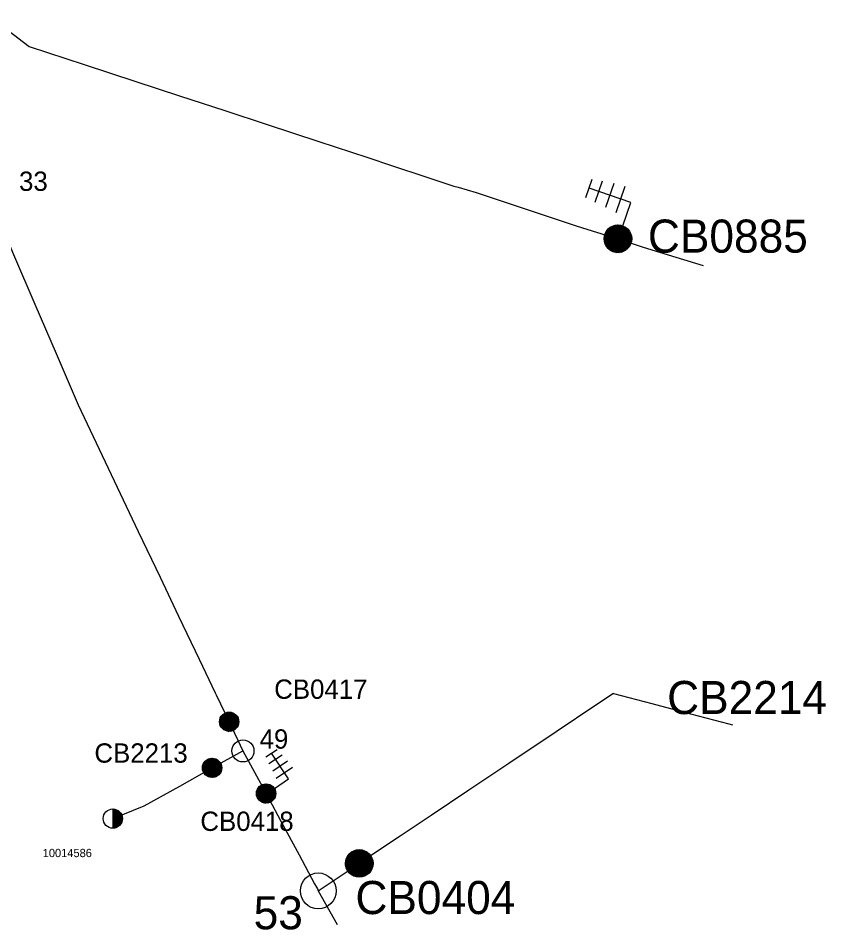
# Model space of a CAD drawing. Extents: x -763722 to -759486, y -1156407 to -1150938.
# Drawn here: x -760950 to -759486, y -1156407 to -1154755 of the extents above; entities that cross this region are included whole.
import ezdxf

# ---------------------------------------------------------------- set-up
doc = ezdxf.new("R2010")
doc.units = 0
for name, color, linetype in [('Default', 7, 'Continuous'), ('Vrstva 1', 7, 'Continuous'), ('Vrstva 2', 7, 'Continuous'), ('Vrstva 3', 7, 'Continuous'), ('Vrstva 5', 7, 'Continuous')]:
    doc.layers.add(name, color=color, linetype=linetype)

# ---------------------------------------------------------------- blocks, each defined once
blk = doc.blocks.new('PS120')
at = {"layer": 'Default'}
for p, q in [((-17.5, -1), (1, 17.5)), ((-17.5, 0.4), (-0.4, 17.5)), ((-17.4, 1.9), (-1.9, 17.4)), ((-17.3, -2.3), (2.3, 17.3)), ((-17.1, -3.5), (3.5, 17.1)), ((-17.1, 3.6), (-3.6, 17.1)), ((-16.9, -4.6), (4.6, 16.9)), ((-16.6, 5.5), (-5.5, 16.6)), ((-16.5, -5.7), (5.7, 16.5)), ((-16.1, -6.7), (6.7, 16.1)), ((-15.7, -7.7), (7.7, 15.7)), ((-15.6, 8), (-8, 15.6)), ((-15.2, -8.6), (8.6, 15.2)), ((-14.7, -9.5), (9.5, 14.7)), ((-14.1, -10.4), (10.4, 14.1)), ((-13.5, -11.1), (11.1, 13.5)), ((-12.8, -11.9), (11.9, 12.8)), ((-12.1, -12.6), (12.6, 12.1)), ((-11.4, -13.3), (13.3, 11.4)), ((-10.6, -13.9), (13.9, 10.6)), ((-9.8, -14.5), (14.5, 9.8)), ((-8.9, -15.1), (15.1, 8.9)), ((-8, -15.6), (15.6, 8)), ((-7, -16), (16, 7)), ((-6, -16.4), (16.4, 6)), ((-5, -16.8), (16.8, 5)), ((-3.8, -17.1), (17.1, 3.8)), ((-2.6, -17.3), (17.3, 2.6)), ((-1.4, -17.4), (17.4, 1.4)), ((0, -17.5), (17.5, 0)), ((1.5, -17.4), (17.4, -1.5)), ((3.1, -17.2), (17.2, -3.1)), ((4.9, -16.8), (16.8, -4.9)), ((7.2, -15.9), (15.9, -7.2)), ((10.8, -13.8), (13.8, -10.8))]:
    blk.add_line(p, q, dxfattribs=at)
for points in [[(-55.4, 36.3), (-55.4, 61)], [(-42.4, 34.3), (-42.4, 63)], [(-27.6, 32.8), (-27.6, 65)], [(-13.1, 30.8), (-13.1, 66.1)], [(0.6, 48.6), (-55.2, 48.7)], [(0.6, 17.6), (0.6, 48.6)]]:
    blk.add_lwpolyline(points, dxfattribs=at)
blk.add_circle((0, 0), 17.5, dxfattribs=at)
blk = doc.blocks.new('PS140')
at = {"layer": 'Default'}
for p, q in [((-17.5, 0), (0, 17.5)), ((-17.4, -1.4), (1.4, 17.4)), ((-17.4, 1.5), (-1.5, 17.4)), ((-17.3, -2.6), (2.6, 17.3)), ((-17.2, 3.1), (-3.1, 17.2)), ((-17.1, -3.8), (3.8, 17.1)), ((-16.8, -4.9), (4.9, 16.8)), ((-16.8, 5), (-5, 16.8)), ((-16.4, -6), (6, 16.4)), ((-16, -7), (7, 16)), ((-15.9, 7.2), (-7.2, 15.9)), ((-15.6, -8), (8, 15.6)), ((-15.1, -8.9), (8.9, 15.1)), ((-14.5, -9.8), (9.8, 14.5)), ((-13.9, -10.6), (10.6, 13.9)), ((-13.8, 10.8), (-10.8, 13.8)), ((-13.3, -11.4), (11.4, 13.3)), ((-12.6, -12.1), (12.1, 12.6)), ((-11.9, -12.8), (12.8, 11.9)), ((-11.2, -13.5), (13.5, 11.2)), ((-10.4, -14.1), (14.1, 10.4)), ((-9.5, -14.7), (14.7, 9.5)), ((-8.6, -15.2), (15.2, 8.6)), ((-7.7, -15.7), (15.7, 7.7)), ((-6.7, -16.1), (16.1, 6.7)), ((-5.7, -16.5), (16.5, 5.7)), ((-4.6, -16.9), (16.9, 4.6)), ((-3.5, -17.1), (17.1, 3.5)), ((-2.3, -17.3), (17.3, 2.3)), ((-1, -17.5), (17.5, 1)), ((0.4, -17.5), (17.5, -0.4)), ((1.9, -17.4), (17.4, -1.9)), ((3.6, -17.1), (17.1, -3.6)), ((5.5, -16.6), (16.6, -5.5)), ((8, -15.6), (15.6, -8))]:
    blk.add_line(p, q, dxfattribs=at)
blk.add_circle((0, 0), 17.5, dxfattribs=at)
blk = doc.blocks.new('PS400')
at = {"layer": 'Default'}
for p, q in [((-25, 0.1), (-0.1, 25)), ((-24.9, -1.2), (1.2, 24.9)), ((-24.9, 1.6), (-1.6, 24.9)), ((-24.8, -2.6), (2.6, 24.8)), ((-24.8, 3.2), (-3.2, 24.8)), ((-24.7, -3.8), (3.8, 24.7)), ((-24.5, -5), (5, 24.5)), ((-24.5, 4.9), (-4.9, 24.5)), ((-24.2, -6.2), (6.2, 24.2)), ((-24.1, 6.7), (-6.7, 24.1)), ((-23.9, -7.3), (7.3, 23.9)), ((-23.6, -8.3), (8.3, 23.6)), ((-23.4, 8.8), (-8.8, 23.4)), ((-23.2, -9.4), (9.4, 23.2)), ((-22.7, -10.3), (10.3, 22.7)), ((-22.3, -11.3), (11.3, 22.3)), ((-22.3, 11.3), (-11.3, 22.3)), ((-21.8, -12.2), (12.2, 21.8)), ((-21.3, -13.1), (13.1, 21.3)), ((-20.7, -14), (14, 20.7)), ((-20.1, -14.8), (14.8, 20.1)), ((-19.9, 15.2), (-15.2, 19.9)), ((-19.5, -15.6), (15.6, 19.5)), ((-18.9, -16.4), (16.4, 18.9)), ((-18.2, -17.1), (17.1, 18.2)), ((-17.5, -17.8), (17.8, 17.5)), ((-16.8, -18.5), (18.5, 16.8)), ((-16, -19.2), (19.2, 16)), ((-15.2, -19.8), (19.8, 15.2)), ((-14.4, -20.4), (20.4, 14.4)), ((-13.6, -21), (21, 13.6)), ((-12.7, -21.5), (21.5, 12.7)), ((-11.8, -22), (22, 11.8)), ((-10.8, -22.5), (22.5, 10.8)), ((-9.9, -22.9), (22.9, 9.9)), ((-8.9, -23.4), (23.4, 8.9)), ((-7.8, -23.7), (23.7, 7.8)), ((-6.7, -24.1), (24.1, 6.7)), ((-5.6, -24.3), (24.3, 5.6)), ((-4.4, -24.6), (24.6, 4.4)), ((-3.2, -24.8), (24.8, 3.2)), ((-1.9, -24.9), (24.9, 1.9)), ((-0.6, -25), (25, 0.6)), ((0.8, -25), (25, -0.8)), ((2.3, -24.9), (24.9, -2.3)), ((4, -24.7), (24.7, -4)), ((5.7, -24.3), (24.3, -5.7)), ((7.7, -23.8), (23.8, -7.7)), ((10, -22.9), (22.9, -10)), ((12.9, -21.4), (21.4, -12.9))]:
    blk.add_line(p, q, dxfattribs=at)
blk.add_circle((0, 0), 25, dxfattribs=at)
blk = doc.blocks.new('PS420')
at = {"layer": 'Default'}
for p, q in [((-25, -0.3), (0.3, 25)), ((-25, 1.2), (-1.2, 25)), ((-24.9, -1.6), (1.6, 24.9)), ((-24.8, -2.9), (2.9, 24.8)), ((-24.8, 2.7), (-2.7, 24.8)), ((-24.6, -4.2), (4.2, 24.6)), ((-24.6, 4.4), (-4.4, 24.6)), ((-24.4, -5.3), (5.3, 24.4)), ((-24.2, 6.2), (-6.2, 24.2)), ((-24.1, -6.5), (6.5, 24.1)), ((-23.8, -7.6), (7.6, 23.8)), ((-23.6, 8.2), (-8.2, 23.6)), ((-23.4, -8.6), (8.6, 23.4)), ((-23, -9.6), (9.6, 23)), ((-22.6, -10.6), (10.6, 22.6)), ((-22.6, 10.6), (-10.6, 22.6)), ((-22.1, -11.6), (11.6, 22.1)), ((-21.6, -12.5), (12.5, 21.6)), ((-21.1, -13.4), (13.4, 21.1)), ((-20.8, 13.8), (-13.8, 20.8)), ((-20.5, -14.2), (14.2, 20.5)), ((-19.9, -15), (15, 19.9)), ((-19.3, -15.8), (15.8, 19.3)), ((-18.7, -16.6), (16.6, 18.7)), ((-18, -17.3), (17.3, 18)), ((-17.3, -18), (18, 17.3)), ((-16.6, -18.7), (18.7, 16.6)), ((-15.8, -19.4), (19.4, 15.8)), ((-15, -20), (20, 15)), ((-14.2, -20.6), (20.6, 14.2)), ((-13.3, -21.1), (21.1, 13.3)), ((-12.4, -21.7), (21.7, 12.4)), ((-11.5, -22.2), (22.2, 11.5)), ((-10.6, -22.6), (22.6, 10.6)), ((-9.6, -23.1), (23.1, 9.6)), ((-8.6, -23.5), (23.5, 8.6)), ((-7.5, -23.8), (23.8, 7.5)), ((-6.4, -24.1), (24.1, 6.4)), ((-5.3, -24.4), (24.4, 5.3)), ((-4.1, -24.6), (24.6, 4.1)), ((-2.9, -24.8), (24.8, 2.9)), ((-1.6, -24.9), (24.9, 1.6)), ((-0.2, -25), (25, 0.2)), ((1.3, -24.9), (24.9, -1.3)), ((2.8, -24.8), (24.8, -2.8)), ((4.4, -24.6), (24.6, -4.4)), ((6.3, -24.2), (24.2, -6.3)), ((8.3, -23.6), (23.6, -8.3)), ((10.7, -22.6), (22.6, -10.7)), ((14, -20.7), (20.7, -14))]:
    blk.add_line(p, q, dxfattribs=at)
for points in [[(-79.1, 51.9), (-79.1, 87.2)], [(-60.6, 49.1), (-60.5, 90)], [(-39.5, 46.8), (-39.4, 92.8)], [(-18.7, 44), (-18.7, 94.4)], [(0.9, 69.5), (-78.8, 69.6)], [(0.8, 25.1), (0.9, 69.5)]]:
    blk.add_lwpolyline(points, dxfattribs=at)
blk.add_circle((0, 0), 25, dxfattribs=at)
blk = doc.blocks.new('PS820')
at = {"layer": 'Vrstva 2'}
blk.add_circle((0, 0), 32.5, dxfattribs=at)
blk = doc.blocks.new('PS610')
at = {"layer": 'Default'}
for p, q in [((0, 16.2), (1.3, 17.4)), ((0, 14.7), (2.5, 17.3)), ((0, 13.3), (3.7, 17.1)), ((0, 11.9), (4.9, 16.8)), ((0, 10.5), (5.9, 16.4)), ((0, 9.1), (7, 16)), ((0, 7.7), (7.9, 15.6)), ((0, 6.3), (8.8, 15.1)), ((0, 4.8), (9.7, 14.5)), ((0, 3.4), (10.5, 14)), ((0, 2), (11.3, 13.3)), ((0, 0.6), (12, 12.7)), ((0, -0.8), (12.8, 12)), ((0, -2.2), (13.4, 11.2)), ((0, -3.6), (14, 10.4)), ((0, -5), (14.6, 9.6)), ((0, -6.5), (15.2, 8.7)), ((0, -7.9), (15.6, 7.8)), ((0, -9.3), (16.1, 6.8)), ((0, -10.7), (16.5, 5.8)), ((0, -12.1), (16.8, 4.7)), ((0, -13.5), (17.1, 3.6)), ((0, -14.9), (17.3, 2.4)), ((0, -16.4), (17.4, 1.1)), ((0.3, -17.5), (17.5, -0.3)), ((1.8, -17.4), (17.4, -1.8)), ((3.5, -17.1), (17.1, -3.5)), ((5.4, -16.7), (16.7, -5.4)), ((7.8, -15.7), (15.6, -7.8))]:
    blk.add_line(p, q, dxfattribs=at)
blk.add_lwpolyline([(0, 17.5), (0, -17.5)], dxfattribs=at)
blk.add_circle((0, 0), 17.5, dxfattribs=at)
blk = doc.blocks.new('PS800')
at = {"layer": 'Vrstva 2'}
blk.add_circle((0, 0), 20, dxfattribs=at)

msp = doc.modelspace()

# ---------------------------------------------------------------- linework, layer by layer
at = {"layer": 'Vrstva 1'}
for points in [[(-760997.9, -1154755.1), (-760930.3, -1154806.5), (-760830.3, -1154839.2), (-760736.9, -1154869.7), (-760657.2, -1154895.7), (-760575.3, -1154922.5), (-760498.3, -1154947.8), (-760404.5, -1154978.5), (-760315.8, -1155007.7), (-760273.3, -1155021.7), (-760210.8, -1155042.3), (-760159.8, -1155059.2), (-760152.4, -1155061.3), (-760119.6, -1155071), (-760079.6, -1155084.4), (-760011, -1155107.2), (-759938.4, -1155131.4), (-759862.5, -1155154.7)], [(-760999.2, -1155088.2), (-760999.2, -1155088.2), (-760999.2, -1155088.3), (-760996.2, -1155095.5), (-760992.2, -1155104.4), (-760958.3, -1155183), (-760919.7, -1155273.5), (-760881.1, -1155362.9), (-760841.1, -1155455.6), (-760732.2, -1155685.6), (-760692.7, -1155768.2), (-760659.1, -1155838.6), (-760621.8, -1155916.5), (-760592.6, -1155977.5), (-760590.8, -1155981.2), (-760567.4, -1156030.1), (-760567.4, -1156030.1)], [(-759862.5, -1155154.7), (-759816.8, -1155169.7), (-759757.6, -1155188.1), (-759708.1, -1155203.5)], [(-759870.7, -1155979), (-759902.3, -1156000.3), (-759974.3, -1156048.7), (-760060.4, -1156106.1), (-760132.6, -1156154.3), (-760201.2, -1156200), (-760257.2, -1156237.2), (-760276.7, -1156250.2), (-760331.5, -1156286.9), (-760331.5, -1156286.9)], [(-759870.7, -1155979), (-759801.2, -1155997.3), (-759730.7, -1156015.9), (-759661.2, -1156034.2), (-759655, -1156035.9)], [(-760567.4, -1156030.1), (-760567.4, -1156030.1), (-760542.4, -1156082.9), (-760542.4, -1156082.9), (-760542.4, -1156082.9)], [(-760598.3, -1156113.7), (-760598.3, -1156113.7), (-760542.4, -1156082.9), (-760542.4, -1156082.9)], [(-760542.4, -1156082.9), (-760542.4, -1156082.9), (-760500.4, -1156160.1), (-760500.4, -1156160.1)], [(-760778.4, -1156205.6), (-760776.6, -1156205), (-760721.7, -1156182.6), (-760657.1, -1156146.6), (-760598.3, -1156113.7), (-760598.3, -1156113.7)], [(-760500.4, -1156160.1), (-760500.4, -1156160.1), (-760473.6, -1156210.6), (-760440.7, -1156271.5), (-760412.7, -1156323.9), (-760407.5, -1156333.1), (-760406, -1156336.3), (-760405.8, -1156336.7), (-760405.8, -1156336.7)], [(-760405.8, -1156336.7), (-760405.8, -1156336.7), (-760405.8, -1156336.7), (-760331.5, -1156286.9), (-760331.5, -1156286.9)], [(-760405.8, -1156336.7), (-760405.8, -1156336.7), (-760371.8, -1156397.7)]]:
    msp.add_lwpolyline(points, dxfattribs=at)

# ---------------------------------------------------------------- block references
at = {"layer": 'Vrstva 2'}
for name, p, rotation in [('PS420', (-759862.5, -1155154.7), -18.99999996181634), ('PS140', (-760567.4, -1156030.1), -65.57321946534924), ('PS120', (-760500.4, -1156160.1), -56.36621943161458), ('PS140', (-760598.3, -1156113.7), -2.0000000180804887), ('PS400', (-760331.5, -1156286.9), 35.00000006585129)]:
    msp.add_blockref(name, p, dxfattribs=dict(at, rotation=rotation))
at = {"layer": 'Vrstva 3'}
msp.add_blockref('PS610', (-760778.4, -1156205.6), dxfattribs=at)
at = {"layer": 'Vrstva 5'}
for name, p, rotation in [('PS800', (-760542.4, -1156082.9), -56.0000000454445), ('PS820', (-760405.8, -1156336.7), -61.99999998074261)]:
    msp.add_blockref(name, p, dxfattribs=dict(at, rotation=rotation))

# ---------------------------------------------------------------- texts
at = {"layer": 'Vrstva 2'}
for s, height, p in [('CB0885', 60, (-759808.1, -1155180)), ('CB0417', 35, (-760485.7, -1155988.6)), ('CB2214', 60, (-759773.2, -1156016.2)), ('CB2213', 35, (-760811.7, -1156104.3)), ('CB0418', 35, (-760619.6, -1156228)), ('CB0404', 60, (-760338.4, -1156378.7))]:
    msp.add_text(s, height=height, dxfattribs=at).set_placement(p)
at = {"layer": 'Vrstva 3'}
msp.add_text('10014586', height=15, dxfattribs=at).set_placement((-760905.5, -1156275.5))
at = {"layer": 'Vrstva 5'}
for s, height, p in [('33', 35, (-760948.4, -1155068)), ('49', 35, (-760512.2, -1156078.9)), ('53', 60, (-760523, -1156406.3))]:
    msp.add_text(s, height=height, dxfattribs=at).set_placement(p)

doc.saveas('drawing.dxf')
